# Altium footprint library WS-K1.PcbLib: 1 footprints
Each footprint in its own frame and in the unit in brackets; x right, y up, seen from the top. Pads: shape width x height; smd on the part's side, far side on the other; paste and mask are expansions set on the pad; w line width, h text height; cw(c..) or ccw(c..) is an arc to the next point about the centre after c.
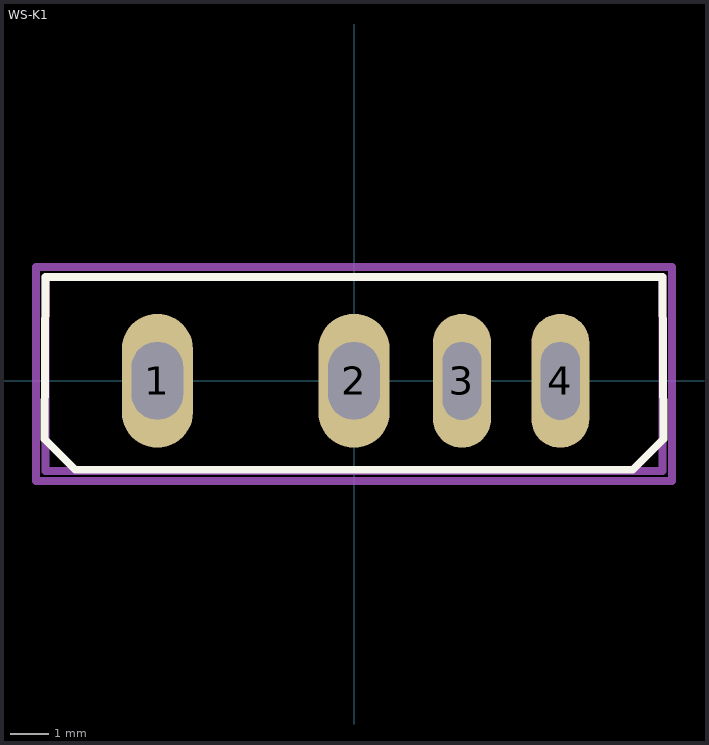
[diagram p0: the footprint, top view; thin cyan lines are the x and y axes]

## WS-K1 [mm] "Wolfspeed K1-package MOSFET"
pads (4):
  oval 1.84x3.46 hole 1.33 slot 2.01 at 90 deg: 1(-5.08,0) 2(0,0)
  oval 1.5x3.46 hole 1 slot 2.01 at 90 deg: 3(2.79,0) 4(5.33,0)
Top Overlay:
  lines w0.203: -8,-1.5 -7.2,-2.3 7.2,-2.3 8,-1.5 7.97,2.685 -7.97,2.685 -8,-1.5
Top Assembly:
  lines w0.203: -7.97,-2.335 7.97,-2.335 7.97,2.685 -7.97,2.685 -7.97,-2.335
Top Courtyard:
  lines w0.203: -8.22,-2.585 8.22,-2.585 8.22,2.935 -8.22,2.935 -8.22,-2.585
3D body "K1_packageZoriented.STEP": height 25.23, standoff -15.75, extent -7.97,-2.335 7.97,2.685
